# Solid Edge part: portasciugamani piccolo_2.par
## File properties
Last saved by: i.fialdini
Revision: 62
Tipo di contenuto documento: 0
Accuracy: 0.990
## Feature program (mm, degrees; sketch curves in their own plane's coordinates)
body "unnamed Body 1"
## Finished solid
Body 1: solid body, 8 faces, 8 edges, 0 vertices.
  Faces by surface: cylinder 4, torus 4
  Edges by curve: circle 8
Bounding box of the edges (mm; curved faces can reach further): 518.000 x 507.500 x 21.000, from (-255.5, -222, -167.5) to (262.5, 285.5, -146.5).
Cylindrical faces by radius (mm): R10.5 x4
Toroidal faces (ring radius, tube radius in mm): R35 r10.5 x4
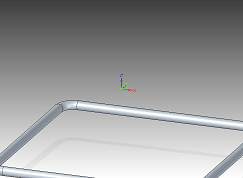
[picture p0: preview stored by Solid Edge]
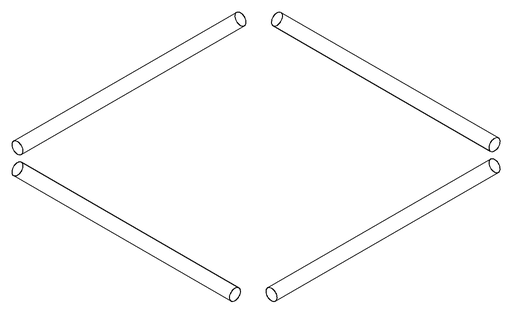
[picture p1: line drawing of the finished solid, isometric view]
